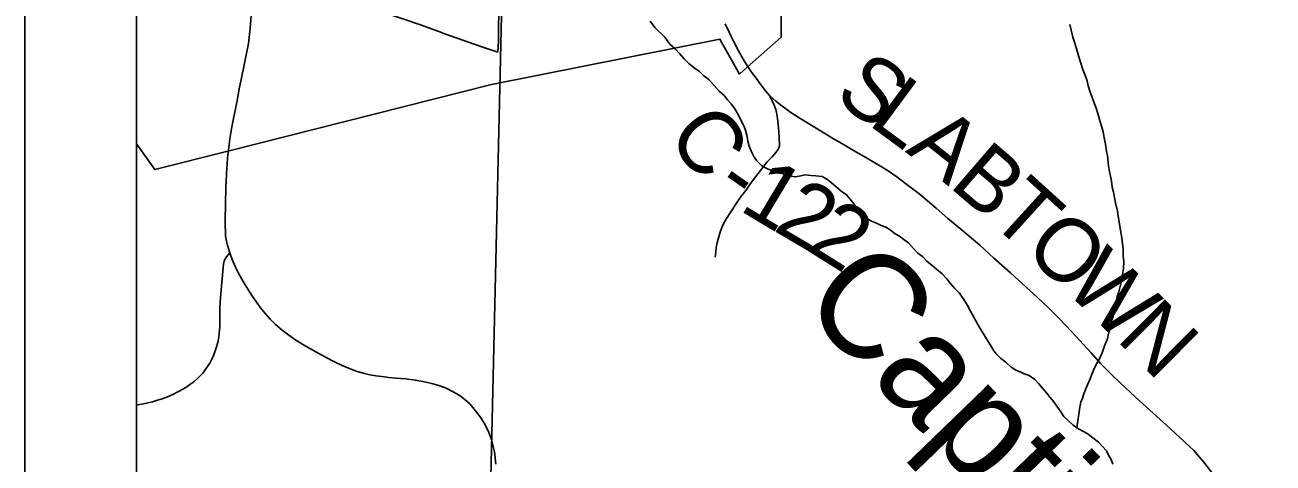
# Model space of a CAD drawing. Extents: x -7.9 to 76.1, y 0 to 22.
# Drawn here: x 2 to 3.119, y 19.828 to 20.221 of the extents above; entities that cross this region are included whole.
import ezdxf

# ---------------------------------------------------------------- set-up
doc = ezdxf.new("R2010")
doc.units = 0
for name, color, linetype in [('GM_X_City_Street', 7, 'Continuous'), ('GM_X_Corporation', 7, 'Continuous'), ('GM_X_County_Road', 7, 'Continuous'), ('GM_X_County_Road_Text', 7, 'Continuous'), ('GM_X_Minor_River', 7, 'Continuous'), ('GM_X_Minor_River_Text', 7, 'Continuous'), ('GM_X_Section', 7, 'Continuous'), ('GM_X_State_Route', 7, 'Continuous'), ('GM_X_Township_Road', 7, 'Continuous'), ('SC_Scratch1', 7, 'Continuous'), ('SH_Data', 7, 'Continuous')]:
    doc.layers.add(name, color=color, linetype=linetype)

msp = doc.modelspace()

# ---------------------------------------------------------------- linework, layer by layer
at = {"layer": 'GM_X_City_Street'}
for points in [[(2.424, 20.1965), (2.4244, 20.2064), (2.4246, 20.221), (2.4256, 20.2557), (2.4257, 20.2683), (2.4254, 20.2859), (2.4257, 20.2946), (2.4261, 20.3013), (2.4259, 20.3063), (2.4255, 20.308)], [(2.2041, 20.2448), (2.2147, 20.2442), (2.2186, 20.244), (2.2418, 20.2432), (2.2545, 20.2427), (2.2747, 20.2418), (2.2813, 20.2415), (2.2842, 20.2413), (2.2874, 20.2409), (2.292, 20.2403), (2.2969, 20.2393), (2.3008, 20.2383), (2.3059, 20.2368), (2.3174, 20.2332), (2.3307, 20.2291), (2.3388, 20.2266), (2.3406, 20.226), (2.3537, 20.2214), (2.3676, 20.2164), (2.3733, 20.2143), (2.3747, 20.2138), (2.4096, 20.2015), (2.424, 20.1965)]]:
    msp.add_lwpolyline(points, dxfattribs=at)
at = {"layer": 'GM_X_Corporation'}
msp.add_lwpolyline([(3.737, 20.9), (2.1, 20.9), (2.1, 20.3255), (2.1391, 20.3247), (2.1182, 20.2751), (2.1, 20.2418), (2.1, 20.1144), (2.1163, 20.0914), (2.1818, 20.1079), (2.4181, 20.1676), (2.623, 20.2083), (2.6405, 20.1769), (2.6475, 20.1831), (2.6778, 20.21), (2.6779, 20.2444), (2.9003, 20.2388), (2.9051, 20.3044), (2.9661, 20.3024), (2.9996, 20.3032), (3.0765, 20.3051), (3.0769, 20.501), (3.408, 20.4821)], dxfattribs=at)
at = {"layer": 'GM_X_County_Road'}
msp.add_line((2.6311, 20.2146), (2.6333, 20.21), dxfattribs=at)
for points in [[(2.6277, 20.2219), (2.6311, 20.2146)], [(2.6333, 20.21), (2.635, 20.2064), (2.6396, 20.1979), (2.6449, 20.1883)], [(2.6449, 20.1883), (2.6486, 20.1828), (2.6513, 20.1788), (2.6553, 20.1732), (2.659, 20.1681), (2.6635, 20.1623), (2.6677, 20.1575), (2.6731, 20.1527), (2.6785, 20.1485), (2.6865, 20.1426), (2.693, 20.1383), (2.7008, 20.1335), (2.713, 20.126), (2.7248, 20.1189), (2.7343, 20.1134), (2.7428, 20.1084), (2.7521, 20.1031), (2.7668, 20.0943), (2.7737, 20.09), (2.7814, 20.0846), (2.7906, 20.078), (2.8012, 20.0697), (2.8167, 20.0565), (2.827, 20.0478), (2.8407, 20.0363), (2.856, 20.0235), (2.8684, 20.0119), (2.8833, 19.9985), (2.8973, 19.9858), (2.9076, 19.9766), (2.9175, 19.9672), (2.9265, 19.9583), (2.9333, 19.9511), (2.9419, 19.9418), (2.9556, 19.9267), (2.964, 19.9173), (2.9679, 19.9132), (2.9741, 19.9071), (2.9816, 19.8999), (2.9955, 19.8871), (3.0113, 19.8728), (3.0269, 19.8585), (3.0436, 19.8432), (3.0476, 19.8392), (3.0511, 19.8353), (3.0566, 19.8287), (3.0736, 19.8066)]]:
    msp.add_lwpolyline(points, dxfattribs=at)
at = {"layer": 'GM_X_Minor_River'}
for points in [[(2.5603, 20.2243), (2.5646, 20.2187), (2.5735, 20.2101), (2.5781, 20.2038), (2.5827, 20.1997), (2.587, 20.1952), (2.5908, 20.1907), (2.595, 20.1866), (2.6, 20.1825), (2.6046, 20.1792), (2.6085, 20.1755), (2.6131, 20.1722), (2.6177, 20.1666), (2.6223, 20.1617), (2.6266, 20.1576), (2.6297, 20.1539), (2.6331, 20.1502), (2.6362, 20.1457), (2.6394, 20.1408), (2.6417, 20.1355), (2.6445, 20.1306), (2.646, 20.1265), (2.6473, 20.1208), (2.6481, 20.1167), (2.6493, 20.1122), (2.6513, 20.1073), (2.6533, 20.1031), (2.6556, 20.0994), (2.6606, 20.0945), (2.6656, 20.092), (2.6701, 20.0902), (2.6751, 20.0884), (2.68, 20.0873), (2.6853, 20.0855), (2.6907, 20.0848), (2.6956, 20.0857), (2.6993, 20.0865), (2.7046, 20.0859), (2.7088, 20.0855), (2.7145, 20.0849), (2.7187, 20.0827), (2.7229, 20.0794), (2.7268, 20.076), (2.7317, 20.0719), (2.7363, 20.0686), (2.7394, 20.0649), (2.7429, 20.0604), (2.7468, 20.0548), (2.7507, 20.0503), (2.7549, 20.0473), (2.7587, 20.0451), (2.7633, 20.0433), (2.7675, 20.0411), (2.7717, 20.0397), (2.7755, 20.0371)], [(2.9365, 20.2215), (2.9394, 20.2102), (2.941, 20.2046), (2.9454, 20.1895), (2.9482, 20.1812), (2.9506, 20.1752), (2.9522, 20.171), (2.953, 20.1665), (2.9546, 20.1616), (2.9586, 20.1503), (2.9601, 20.1465), (2.9617, 20.1416), (2.9633, 20.1363), (2.965, 20.1303), (2.9666, 20.125), (2.9674, 20.1197), (2.9687, 20.1141), (2.9695, 20.1076), (2.9703, 20.1039), (2.9713, 20.0944), (2.9721, 20.0895), (2.9729, 20.0853), (2.9738, 20.0808), (2.9746, 20.0755), (2.9758, 20.071), (2.9767, 20.0661), (2.9775, 20.0615), (2.9792, 20.054), (2.98, 20.0494), (2.9813, 20.0407), (2.9821, 20.0366), (2.9829, 20.0317), (2.9838, 20.0249), (2.9843, 20.0199), (2.9844, 20.0139), (2.9849, 20.0086), (2.9846, 20.0029), (2.9839, 19.9968), (2.9825, 19.99), (2.9804, 19.9816), (2.979, 19.9774), (2.9783, 19.9732), (2.9772, 19.969), (2.9765, 19.9645), (2.9755, 19.9595), (2.9737, 19.9546), (2.9723, 19.9481), (2.9712, 19.9443), (2.9702, 19.9393), (2.9676, 19.9332), (2.9655, 19.9267), (2.9625, 19.9202), (2.9603, 19.9164), (2.9581, 19.9118), (2.9563, 19.9076), (2.9549, 19.9034), (2.9523, 19.8981)], [(2.7755, 20.0371), (2.7801, 20.0337), (2.7839, 20.0315), (2.7877, 20.0286), (2.792, 20.0256), (2.7966, 20.0204), (2.8004, 20.0163), (2.8047, 20.013), (2.8085, 20.0092), (2.8131, 20.0051), (2.817, 20.0018), (2.822, 19.9977), (2.8262, 19.9932), (2.8289, 19.9895), (2.8332, 19.9847), (2.8374, 19.9806), (2.8416, 19.9746), (2.8448, 19.9693), (2.8475, 19.9641), (2.8553, 19.9502), (2.8577, 19.9464), (2.86, 19.9423), (2.8627, 19.9378), (2.8654, 19.9337), (2.8678, 19.9295), (2.8705, 19.9258), (2.8743, 19.9221), (2.8793, 19.9184), (2.8839, 19.9139), (2.8882, 19.9113), (2.892, 19.9099), (2.8958, 19.9081), (2.9, 19.9066), (2.9053, 19.9029), (2.9084, 19.8992), (2.9119, 19.8954), (2.9161, 19.8906), (2.9188, 19.8869), (2.9223, 19.8827), (2.9285, 19.8738), (2.9313, 19.8696), (2.9355, 19.8659), (2.9397, 19.8618), (2.9439, 19.8589), (2.9493, 19.8559), (2.9531, 19.8537), (2.9573, 19.8504), (2.9623, 19.8467), (2.9696, 19.8389), (2.9712, 19.8351), (2.9735, 19.831), (2.9751, 19.8268)], [(2.9523, 19.8981), (2.9505, 19.8939), (2.9491, 19.89), (2.948, 19.8862), (2.9465, 19.8824), (2.9455, 19.8779), (2.943, 19.8595)]]:
    msp.add_lwpolyline(points, dxfattribs=at)
at = {"layer": 'GM_X_Section'}
msp.add_lwpolyline([(3.4482, 20.2963), (3.4168, 19.2711), (2.4057, 19.2962), (2.4291, 20.3209)], close=True, dxfattribs=at)
at = {"layer": 'GM_X_State_Route'}
for points in [[(2.182, 20.1066), (2.1823, 20.1087), (2.1836, 20.1188), (2.1855, 20.1295), (2.1901, 20.1533), (2.1924, 20.1651), (2.1935, 20.1706), (2.2003, 20.2044), (2.202, 20.2182), (2.2041, 20.2448)], [(2.1812, 20.0959), (2.1816, 20.1019), (2.182, 20.1066)], [(2.4221, 19.827), (2.4215, 19.8326), (2.4208, 19.838), (2.4198, 19.8429), (2.4182, 19.8489), (2.4158, 19.8552), (2.4137, 19.8599), (2.4113, 19.8643), (2.408, 19.8694), (2.4039, 19.8748), (2.399, 19.8806), (2.3942, 19.8849), (2.3891, 19.8888), (2.3838, 19.8917), (2.3776, 19.895), (2.3719, 19.8972), (2.3648, 19.8994), (2.3565, 19.9012), (2.3498, 19.9024), (2.341, 19.9034), (2.3323, 19.9041), (2.3261, 19.9048), (2.32, 19.9056), (2.3144, 19.9063), (2.309, 19.9072), (2.3044, 19.9084), (2.2977, 19.9101), (2.2916, 19.9123), (2.2842, 19.9154), (2.2774, 19.9187), (2.2701, 19.9227), (2.2607, 19.9277), (2.2512, 19.9332), (2.2429, 19.9383), (2.2364, 19.9426), (2.2306, 19.9471), (2.2246, 19.9521), (2.2199, 19.9569), (2.2155, 19.9619), (2.211, 19.9672), (2.2083, 19.971), (2.204, 19.9774), (2.1997, 19.984), (2.1957, 19.9907), (2.1918, 19.9977), (2.1885, 20.0042), (2.1858, 20.0105), (2.1836, 20.0164), (2.1814, 20.0233), (2.1807, 20.0271), (2.1799, 20.0318), (2.1794, 20.0446), (2.1797, 20.0611), (2.1801, 20.0748), (2.1807, 20.0867), (2.181, 20.0929), (2.1812, 20.0959)]]:
    msp.add_lwpolyline(points, dxfattribs=at)
at = {"layer": 'GM_X_Township_Road'}
for points in [[(2.6187, 20.0128), (2.6192, 20.0172), (2.6196, 20.0213), (2.6206, 20.0256), (2.6229, 20.0342), (2.6246, 20.0394), (2.6264, 20.0431), (2.6287, 20.0474), (2.6327, 20.0533), (2.6372, 20.0603), (2.6415, 20.0664), (2.6461, 20.0725), (2.6497, 20.0778), (2.6538, 20.0836), (2.6593, 20.0905), (2.6652, 20.0981), (2.6697, 20.1028), (2.6732, 20.1066), (2.6747, 20.1089), (2.6757, 20.1108), (2.6763, 20.1125), (2.6764, 20.1139), (2.6756, 20.1252), (2.6748, 20.1347), (2.6743, 20.1389), (2.6738, 20.1426), (2.6731, 20.1452), (2.6715, 20.149), (2.6677, 20.1575)], [(2.1, 19.8797), (2.1091, 19.8817), (2.1143, 19.8829), (2.1189, 19.8843), (2.1229, 19.8856), (2.1277, 19.8874), (2.1325, 19.8894), (2.1383, 19.8923), (2.1441, 19.8958), (2.1479, 19.8983), (2.1514, 19.9008), (2.156, 19.9051), (2.1594, 19.9086), (2.1631, 19.9135), (2.1656, 19.9175), (2.1675, 19.921), (2.1693, 19.9251), (2.1715, 19.9312), (2.1728, 19.9362), (2.1738, 19.941), (2.1742, 19.9443), (2.1746, 19.9503), (2.1748, 19.9665), (2.175, 19.9723), (2.1752, 19.9764), (2.1776, 20.0035), (2.178, 20.0065), (2.1787, 20.0092), (2.1796, 20.0112), (2.1806, 20.0129), (2.1836, 20.0164)]]:
    msp.add_lwpolyline(points, dxfattribs=at)
at = {"layer": 'SC_Scratch1'}
msp.add_lwpolyline([(2.1, 20.3271), (2.1, 19.3026), (2.4057, 19.2962), (2.4291, 20.3209)], close=True, dxfattribs=at)
at = {"layer": 'SH_Data'}
for p, q in [((2, 21), (2, 14)), ((2.1, 20.9), (2.1, 14.1))]:
    msp.add_line(p, q, dxfattribs=at)

# ---------------------------------------------------------------- texts
at = {"layer": 'GM_X_County_Road_Text'}
for s, rotation, p in [('S', 323.8238, (2.7238, 20.155)), ('L', 323.5595, (2.7547, 20.1324)), ('C', 307.8527, (2.5742, 20.1209)), ('A', 321.4921, (2.7885, 20.1075)), ('B', 319.2789, (2.8272, 20.0767)), ('1', 329.0759, (2.639, 20.0555)), ('-', 325.1131, (2.6163, 20.0712)), ('T', 317.8041, (2.8623, 20.0465)), ('2', 329.5603, (2.6695, 20.0373)), ('2', 327.8689, (2.6993, 20.0198)), ('O', 317.4271, (2.8937, 20.018)), ('W', 315.9312, (2.9302, 19.9845)), ('N', 315.2808, (2.9774, 19.9388))]:
    msp.add_text(s, height=0.0568, rotation=rotation, dxfattribs=at).set_placement(p)
at = {"layer": 'GM_X_Minor_River_Text'}
msp.add_text('Captina', height=0.09467, rotation=314.0629, dxfattribs=at).set_placement((2.6927, 19.9703))

doc.saveas('drawing.dxf')
